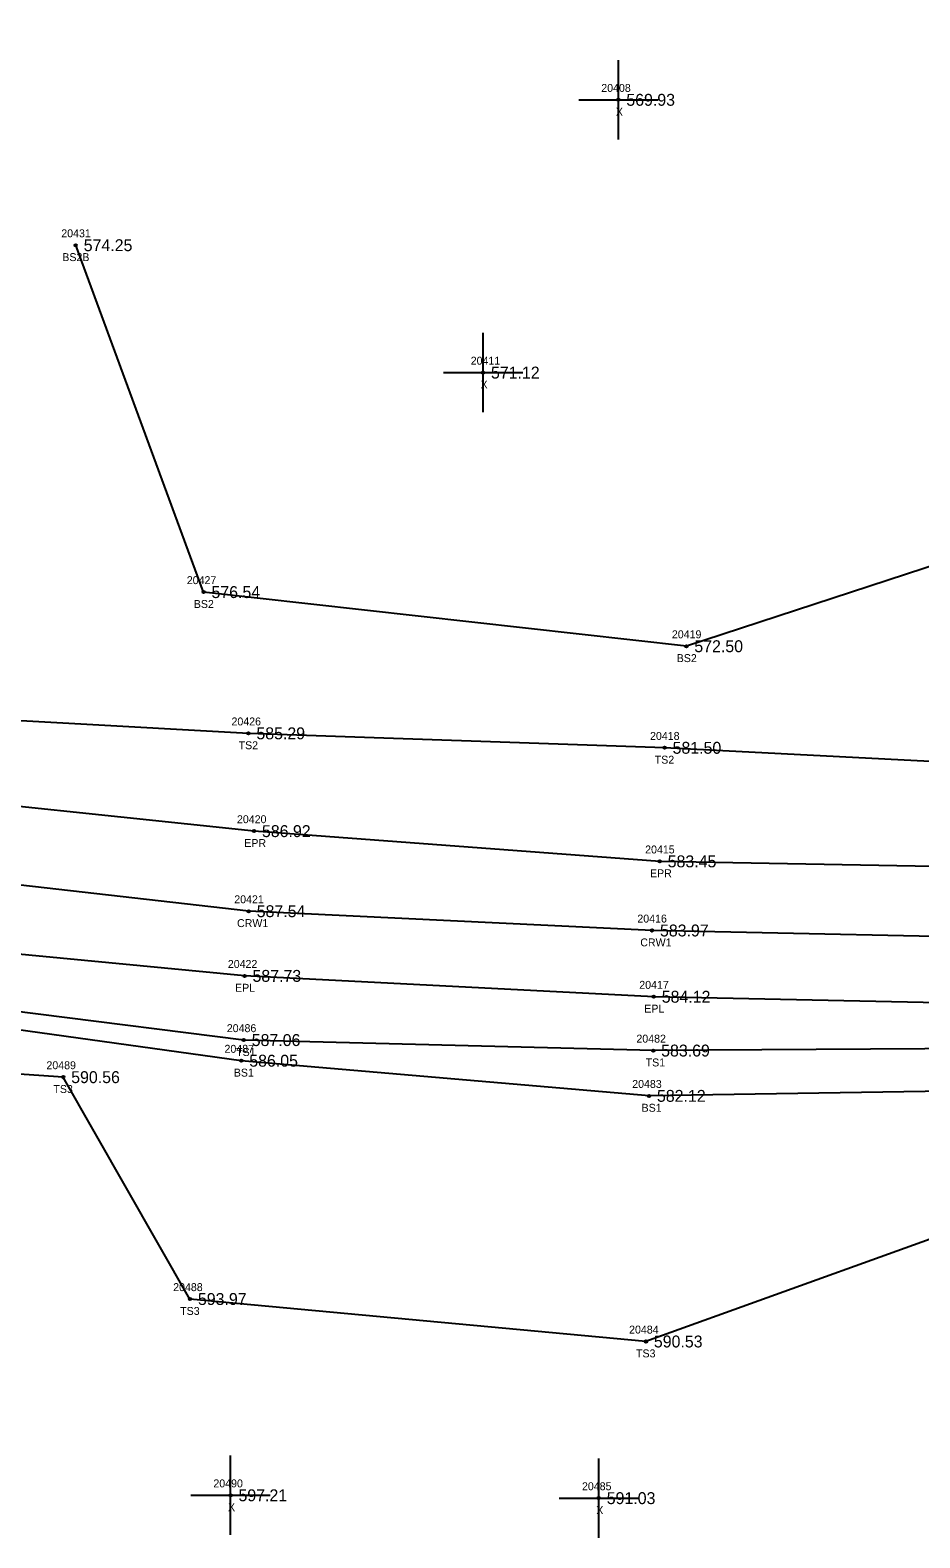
# Model space of a CAD drawing. Extents: x 1530159 to 1531652, y 877045 to 877724.
# Drawn here: x 1530581.3 to 1530693.4, y 877192.7 to 877382.7 of the extents above; entities that cross this region are included whole.
import ezdxf

# ---------------------------------------------------------------- set-up
doc = ezdxf.new("R2010")
doc.units = 0
for name, color, linetype in [('RD_DTM_BkLn1', 7, 'Continuous'), ('RD_DTM_BkLn2', 7, 'Continuous'), ('RD_DTM_BkLn_txCode', 7, 'Continuous'), ('RD_EX_Misc', 7, 'Continuous'), ('RD_EX_Misc_txCode', 7, 'Continuous'), ('RD_EX_Road', 7, 'Continuous'), ('RD_EX_Road_txCode', 7, 'Continuous'), ('RD_EX_TX_Misc_ELEV', 7, 'Continuous'), ('RD_EX_TX_Road_ELEV', 7, 'Continuous'), ('RD_HC_Survey_ELEV', 7, 'Continuous'), ('RD_HC_Survey_txCode', 7, 'Continuous'), ('RD_SMD_Locator', 7, 'Continuous')]:
    doc.layers.add(name, color=color, linetype=linetype)

msp = doc.modelspace()

# ---------------------------------------------------------------- linework, layer by layer
at = {"layer": 'RD_DTM_BkLn1'}
msp.add_lwpolyline([(1530865.56, 877271.01), (1530814.96, 877268.2), (1530763.15, 877267.89), (1530711.13, 877268.14), (1530659.67, 877269.22), (1530608.85, 877271.65), (1530559.07, 877277.33), (1530509.18, 877284.07), (1530458.44, 877292.62), (1530408.04, 877304.59), (1530358.54, 877316.67), (1530308.57, 877330.02), (1530250.23, 877350.32), (1530188.17, 877372.62)], dxfattribs=at)
at = {"layer": 'RD_DTM_BkLn2'}
for points in [[(1530846.55, 877195.51), (1530836.44, 877218.02), (1530825.43, 877234.54), (1530809.73, 877254.08), (1530787.3, 877254.89), (1530761.32, 877254.01), (1530707.75, 877254.4), (1530659.82, 877254.09), (1530608.22, 877255.41), (1530556.36, 877261.96), (1530505.86, 877268.16), (1530455.53, 877277.54), (1530404.07, 877287.69), (1530355.59, 877301.63), (1530305.18, 877312.26), (1530242.86, 877334.32), (1530183.05, 877357.3)], [(1530843.03, 877194.57), (1530830.04, 877216.97), (1530814.8, 877230.65), (1530802.93, 877234.88), (1530787.62, 877244.18), (1530761.15, 877248.01), (1530710.15, 877249.2), (1530659.29, 877248.38), (1530607.91, 877252.81), (1530555.6, 877260.07), (1530504.64, 877266.43), (1530454.3, 877275.47), (1530403.13, 877286.43), (1530354.95, 877299.51), (1530304.97, 877310.18), (1530241.94, 877332.54), (1530182.43, 877355.46)], [(1530775.76, 877331.65), (1530781.99, 877302.01), (1530765.52, 877300.73), (1530698.54, 877316.36), (1530664, 877305.04), (1530603.15, 877311.86), (1530587.05, 877355.57)], [(1530780.69, 877332.06), (1530788.09, 877307.32), (1530788.66, 877295.54), (1530766.14, 877289.81), (1530711.07, 877289.67), (1530661.26, 877292.24), (1530608.81, 877294.06), (1530562.73, 877296.61), (1530511.3, 877298), (1530460.71, 877306.98), (1530411.43, 877318.55), (1530362.64, 877330.57), (1530303.69, 877348.12), (1530304.27, 877353.11), (1530308.16, 877353.44)], [(1530781.59, 877237.74), (1530769.19, 877234.54), (1530707.91, 877235.08), (1530658.9, 877217.43), (1530601.44, 877222.78), (1530585.47, 877250.74), (1530554.71, 877252.85), (1530502.71, 877258.91), (1530451.66, 877269.63), (1530401.38, 877279.82), (1530344.51, 877291.95), (1530339.77, 877285.8), (1530357.81, 877267.08), (1530377.75, 877244.03)]]:
    msp.add_lwpolyline(points, dxfattribs=at)
at = {"layer": 'RD_EX_Misc'}
for p, q in [((1530655.43, 877368.89), (1530655.43, 877378.89)), ((1530650.43, 877373.89), (1530660.43, 877373.89)), ((1530638.37, 877334.52), (1530638.37, 877344.52)), ((1530633.37, 877339.52), (1530643.37, 877339.52)), ((1530606.55, 877193.05), (1530606.55, 877203.05)), ((1530652.96, 877192.69), (1530652.96, 877202.69)), ((1530601.55, 877198.05), (1530611.55, 877198.05)), ((1530647.96, 877197.69), (1530657.96, 877197.69))]:
    msp.add_line(p, q, dxfattribs=at)
at = {"layer": 'RD_EX_Road'}
for points in [[(1530865.35, 877283.66), (1530865.36, 877280.61), (1530815.01, 877277.89), (1530763.54, 877277.33), (1530711.24, 877277.01), (1530660.64, 877277.93), (1530609.51, 877281.74), (1530559.88, 877286.96), (1530511.03, 877294.4), (1530460.35, 877303.35), (1530410.49, 877314.53), (1530361.04, 877326.77), (1530310.59, 877340.83), (1530305.81, 877342.41), (1530288.71, 877347.95), (1530253.55, 877359.27), (1530192.32, 877382.67)], [(1530866.41, 877261.44), (1530852.87, 877260.97), (1530806.23, 877259.4), (1530762.44, 877259.05), (1530711.8, 877259.77), (1530659.89, 877260.87), (1530608.32, 877263.5), (1530557.85, 877268.33), (1530507.29, 877275.71), (1530456.72, 877284.51), (1530406.3, 877294.52), (1530356.75, 877305.76), (1530307.05, 877320.51), (1530246, 877341.34), (1530185.26, 877363.97)]]:
    msp.add_lwpolyline(points, dxfattribs=at)
at = {"layer": 'RD_SMD_Locator'}
for centre in [(1530655.43, 877373.89), (1530587.05, 877355.57), (1530638.37, 877339.52), (1530603.15, 877311.86), (1530664, 877305.04), (1530608.81, 877294.06), (1530661.26, 877292.24), (1530609.51, 877281.74), (1530660.64, 877277.93), (1530608.85, 877271.65), (1530659.67, 877269.22), (1530608.32, 877263.5), (1530659.89, 877260.87), (1530608.22, 877255.41), (1530659.82, 877254.09), (1530607.91, 877252.81), (1530585.47, 877250.74), (1530659.29, 877248.38), (1530601.44, 877222.78), (1530658.9, 877217.43), (1530606.55, 877198.05), (1530652.96, 877197.69)]:
    msp.add_circle(centre, 0.15, dxfattribs=at)

# ---------------------------------------------------------------- texts
at = {"layer": 'RD_DTM_BkLn_txCode'}
for s, p in [('20431', (1530585.22, 877356.57)), ('BS2B', (1530585.35, 877353.57)), ('20427', (1530601.04, 877312.86)), ('BS2', (1530601.92, 877309.86)), ('20419', (1530662.17, 877306.04)), ('BS2', (1530662.78, 877303.04)), ('20426', (1530606.67, 877295.06)), ('20418', (1530659.42, 877293.24)), ('TS2', (1530607.57, 877292.06)), ('TS2', (1530660.01, 877290.24)), ('20486', (1530606.08, 877256.41)), ('20482', (1530657.7, 877255.09)), ('20487', (1530605.79, 877253.81)), ('TS1', (1530607.26, 877253.41)), ('20489', (1530583.35, 877251.74)), ('TS1', (1530658.86, 877252.09)), ('BS1', (1530606.96, 877250.81)), ('20483', (1530657.17, 877249.38)), ('TS3', (1530584.23, 877248.74)), ('BS1', (1530658.35, 877246.38)), ('20488', (1530599.32, 877223.78)), ('TS3', (1530600.2, 877220.78)), ('20484', (1530656.78, 877218.43)), ('TS3', (1530657.65, 877215.43))]:
    msp.add_text(s, height=1, dxfattribs=at).set_placement(p)
at = {"layer": 'RD_EX_Misc_txCode'}
for s, p in [('20408', (1530653.27, 877374.89)), ('X', (1530655.11, 877371.89)), ('20411', (1530636.82, 877340.52)), ('X', (1530638.06, 877337.52)), ('20490', (1530604.39, 877199.05)), ('20485', (1530650.84, 877198.69)), ('X', (1530606.23, 877196.05)), ('X', (1530652.64, 877195.69))]:
    msp.add_text(s, height=1, dxfattribs=at).set_placement(p)
at = {"layer": 'RD_EX_Road_txCode'}
for s, p in [('20420', (1530607.36, 877282.74)), ('EPR', (1530608.28, 877279.74)), ('20415', (1530658.8, 877278.93)), ('EPR', (1530659.41, 877275.93)), ('20422', (1530606.21, 877264.5)), ('EPL', (1530607.12, 877261.5)), ('20417', (1530658.06, 877261.87)), ('EPL', (1530658.69, 877258.87))]:
    msp.add_text(s, height=1, dxfattribs=at).set_placement(p)
at = {"layer": 'RD_EX_TX_Misc_ELEV'}
for s, p in [('569.93', (1530656.43, 877373.14)), ('574.25', (1530588.05, 877354.82)), ('571.12', (1530639.37, 877338.77)), ('576.54', (1530604.15, 877311.11)), ('572.50', (1530665, 877304.29)), ('585.29', (1530609.81, 877293.31)), ('581.50', (1530662.26, 877291.49)), ('587.06', (1530609.22, 877254.66)), ('583.69', (1530660.82, 877253.34)), ('586.05', (1530608.91, 877252.06)), ('590.56', (1530586.47, 877249.99)), ('582.12', (1530660.29, 877247.63)), ('593.97', (1530602.44, 877222.03)), ('590.53', (1530659.9, 877216.68)), ('597.21', (1530607.55, 877197.3)), ('591.03', (1530653.96, 877196.94))]:
    msp.add_text(s, height=1.5, dxfattribs=at).set_placement(p)
at = {"layer": 'RD_EX_TX_Road_ELEV'}
for s, p in [('586.92', (1530610.51, 877280.99)), ('583.45', (1530661.64, 877277.18)), ('587.73', (1530609.32, 877262.75)), ('584.12', (1530660.89, 877260.12))]:
    msp.add_text(s, height=1.5, dxfattribs=at).set_placement(p)
at = {"layer": 'RD_HC_Survey_ELEV'}
for s, p in [('587.54', (1530609.85, 877270.9)), ('583.97', (1530660.67, 877268.47))]:
    msp.add_text(s, height=1.5, dxfattribs=at).set_placement(p)
at = {"layer": 'RD_HC_Survey_txCode'}
for s, p in [('20421', (1530607.02, 877272.65)), ('20416', (1530657.82, 877270.22)), ('CRW1', (1530607.37, 877269.65)), ('CRW1', (1530658.19, 877267.22))]:
    msp.add_text(s, height=1, dxfattribs=at).set_placement(p)

doc.saveas('drawing.dxf')
